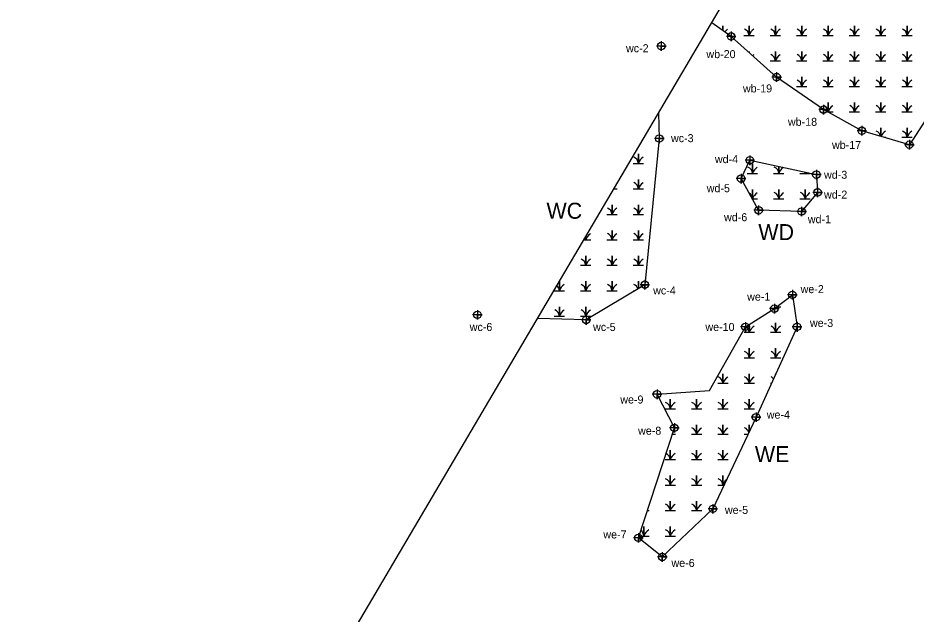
# Model space of a CAD drawing. Extents: x 2379288 to 2381905, y 330670 to 333511.
# Drawn here: x 2379288 to 2379849, y 331240 to 331613 of the extents above; entities that cross this region are included whole.
import ezdxf

# ---------------------------------------------------------------- set-up
doc = ezdxf.new("R2010")
doc.units = 0
for name, color, linetype in [('Default', 7, 'Continuous'), ('Exist Environmental Wetland Boundary', 7, 'Continuous'), ('Exist Environmental Wetland Boundary Cogo Number', 7, 'Continuous'), ('Exist Environmental Wetland Boundary Cogo Point CELL', 7, 'Continuous'), ('Exist Environmental Wetland Boundary Text', 7, 'Continuous'), ('Exist Hydro Swamp or Marsh', 7, 'Continuous')]:
    doc.layers.add(name, color=color, linetype=linetype)

msp = doc.modelspace()

# ---------------------------------------------------------------- linework, layer by layer
at = {"layer": 'Default'}
msp.add_lwpolyline([(2380453.94, 332065.55), (2379632.78, 330670.47), (2379288.07, 330873.37), (2380109.3, 332268.58)], dxfattribs=at)
at = {"layer": 'Exist Environmental Wetland Boundary'}
for points in [[(2380130.29, 332029.9), (2380102.32, 331972.59), (2380055.88, 331898.56), (2380034.74, 331855.71), (2379997.28, 331799.99), (2379955.67, 331743.45), (2379938.98, 331697.47), (2379905.07, 331626.66), (2379844.93, 331533.46), (2379815.25, 331542.18), (2379791.29, 331555.41), (2379761.99, 331575.7), (2379733.64, 331601.14), (2379721.48, 331609.71)], [(2379688.21, 331553.19), (2379688.73, 331537.29), (2379679.7, 331445.96), (2379643.04, 331423.91), (2379612.62, 331424.77)]]:
    msp.add_lwpolyline(points, dxfattribs=at)
for points in [[(2379777.65, 331491.7), (2379750.74, 331492.47), (2379739.83, 331512.28), (2379745.27, 331523.73), (2379786.87, 331514.73), (2379787.62, 331503.6)], [(2379760.62, 331430.97), (2379771.84, 331439.64), (2379774.79, 331419.58), (2379749.19, 331363.16), (2379722.16, 331305.85), (2379690.58, 331275.83), (2379675.68, 331287.73), (2379698.12, 331356.48), (2379687.35, 331377.45), (2379720.1, 331379.72), (2379742.49, 331419.61)]]:
    msp.add_lwpolyline(points, close=True, dxfattribs=at)
at = {"layer": 'Exist Environmental Wetland Boundary Cogo Point CELL'}
for points in [[(2379733.64, 331604.14), (2379733.64, 331598.14), (2379733.64, 331601.14), (2379736.64, 331601.14), (2379730.64, 331601.14)], [(2379689.98, 331598.11), (2379689.98, 331592.11), (2379689.98, 331595.11), (2379692.98, 331595.11), (2379686.98, 331595.11)], [(2379761.99, 331578.7), (2379761.99, 331572.7), (2379761.99, 331575.7), (2379764.99, 331575.7), (2379758.99, 331575.7)], [(2379791.29, 331558.41), (2379791.29, 331552.41), (2379791.29, 331555.41), (2379794.29, 331555.41), (2379788.29, 331555.41)], [(2379815.25, 331545.18), (2379815.25, 331539.18), (2379815.25, 331542.18), (2379818.25, 331542.18), (2379812.25, 331542.18)], [(2379688.73, 331540.29), (2379688.73, 331534.29), (2379688.73, 331537.29), (2379691.73, 331537.29), (2379685.73, 331537.29)], [(2379844.93, 331536.46), (2379844.93, 331530.46), (2379844.93, 331533.46), (2379847.93, 331533.46), (2379841.93, 331533.46)], [(2379745.27, 331526.73), (2379745.27, 331520.73), (2379745.27, 331523.73), (2379748.27, 331523.73), (2379742.27, 331523.73)], [(2379739.83, 331515.28), (2379739.83, 331509.28), (2379739.83, 331512.28), (2379742.83, 331512.28), (2379736.83, 331512.28)], [(2379786.87, 331517.73), (2379786.87, 331511.73), (2379786.87, 331514.73), (2379789.87, 331514.73), (2379783.87, 331514.73)], [(2379787.62, 331506.6), (2379787.62, 331500.6), (2379787.62, 331503.6), (2379790.62, 331503.6), (2379784.62, 331503.6)], [(2379750.74, 331495.47), (2379750.74, 331489.47), (2379750.74, 331492.47), (2379753.74, 331492.47), (2379747.74, 331492.47)], [(2379777.65, 331494.7), (2379777.65, 331488.7), (2379777.65, 331491.7), (2379780.65, 331491.7), (2379774.65, 331491.7)], [(2379679.7, 331448.96), (2379679.7, 331442.96), (2379679.7, 331445.96), (2379682.7, 331445.96), (2379676.7, 331445.96)], [(2379771.84, 331442.64), (2379771.84, 331436.64), (2379771.84, 331439.64), (2379774.84, 331439.64), (2379768.84, 331439.64)], [(2379575.08, 331430.12), (2379575.08, 331424.12), (2379575.08, 331427.12), (2379578.08, 331427.12), (2379572.08, 331427.12)], [(2379760.62, 331433.97), (2379760.62, 331427.97), (2379760.62, 331430.97), (2379763.62, 331430.97), (2379757.62, 331430.97)], [(2379643.04, 331426.91), (2379643.04, 331420.91), (2379643.04, 331423.91), (2379646.04, 331423.91), (2379640.04, 331423.91)], [(2379742.49, 331422.61), (2379742.49, 331416.61), (2379742.49, 331419.61), (2379745.49, 331419.61), (2379739.49, 331419.61)], [(2379774.79, 331422.58), (2379774.79, 331416.58), (2379774.79, 331419.58), (2379777.79, 331419.58), (2379771.79, 331419.58)], [(2379687.35, 331380.45), (2379687.35, 331374.45), (2379687.35, 331377.45), (2379690.35, 331377.45), (2379684.35, 331377.45)], [(2379749.19, 331366.16), (2379749.19, 331360.16), (2379749.19, 331363.16), (2379752.19, 331363.16), (2379746.19, 331363.16)], [(2379698.12, 331359.48), (2379698.12, 331353.48), (2379698.12, 331356.48), (2379701.12, 331356.48), (2379695.12, 331356.48)], [(2379722.16, 331308.85), (2379722.16, 331302.85), (2379722.16, 331305.85), (2379725.16, 331305.85), (2379719.16, 331305.85)], [(2379675.68, 331290.73), (2379675.68, 331284.73), (2379675.68, 331287.73), (2379678.68, 331287.73), (2379672.68, 331287.73)], [(2379690.58, 331278.83), (2379690.58, 331272.83), (2379690.58, 331275.83), (2379693.58, 331275.83), (2379687.58, 331275.83)]]:
    msp.add_lwpolyline(points, dxfattribs=at)
for centre in [(2379733.64, 331601.14), (2379689.98, 331595.11), (2379761.99, 331575.7), (2379791.29, 331555.41), (2379815.25, 331542.18), (2379688.73, 331537.29), (2379844.93, 331533.46), (2379745.27, 331523.73), (2379739.83, 331512.28), (2379786.87, 331514.73), (2379787.62, 331503.6), (2379750.74, 331492.47), (2379777.65, 331491.7), (2379679.7, 331445.96), (2379771.84, 331439.64), (2379575.08, 331427.12), (2379760.62, 331430.97), (2379643.04, 331423.91), (2379742.49, 331419.61), (2379774.79, 331419.58), (2379687.35, 331377.45), (2379749.19, 331363.16), (2379698.12, 331356.48), (2379722.16, 331305.85), (2379675.68, 331287.73), (2379690.58, 331275.83)]:
    msp.add_circle(centre, 2.34, dxfattribs=at)
at = {"layer": 'Exist Hydro Swamp or Marsh'}
for p, q in [((2379829.24, 331538.07), (2379830.29, 331538.07)), ((2379660.34, 331505.83), (2379662.46, 331505.83)), ((2379672.46, 331442.16), (2379673.37, 331442.16)), ((2379762.11, 331432.12), (2379764.57, 331432.12)), ((2379731.64, 331400.28), (2379731.67, 331400.28)), ((2379758.12, 331384.36), (2379758.81, 331384.36)), ((2379696.83, 331352.53), (2379698.77, 331352.53)), ((2379741.67, 331352.53), (2379744.18, 331352.53)), ((2379681.25, 331304.77), (2379682.31, 331304.77))]:
    msp.add_line(p, q, dxfattribs=at)
for points in [[(2379728.35, 331604.87), (2379728.35, 331607.66), (2379728.35, 331604.87)], [(2379741.58, 331601.74), (2379744.81, 331601.74), (2379744.81, 331607.66), (2379744.81, 331601.74), (2379748.03, 331601.74)], [(2379758.03, 331601.74), (2379761.26, 331601.74), (2379761.26, 331607.66), (2379761.26, 331601.74), (2379764.48, 331601.74)], [(2379774.48, 331601.74), (2379777.71, 331601.74), (2379777.71, 331607.66), (2379777.71, 331601.74), (2379780.93, 331601.74)], [(2379790.93, 331601.74), (2379794.16, 331601.74), (2379794.16, 331607.66), (2379794.16, 331601.74), (2379797.39, 331601.74)], [(2379807.39, 331601.74), (2379810.61, 331601.74), (2379810.61, 331607.66), (2379810.61, 331601.74), (2379813.84, 331601.74)], [(2379823.84, 331601.74), (2379827.06, 331601.74), (2379827.06, 331607.66), (2379827.06, 331601.74), (2379830.29, 331601.74)], [(2379840.29, 331601.74), (2379843.51, 331601.74), (2379843.51, 331607.66), (2379843.51, 331601.74), (2379846.74, 331601.74)], [(2379744.81, 331591.12), (2379744.81, 331591.74), (2379744.81, 331591.12)], [(2379758.03, 331585.82), (2379761.26, 331585.82), (2379761.26, 331591.74), (2379761.26, 331585.82), (2379764.48, 331585.82)], [(2379774.48, 331585.82), (2379777.71, 331585.82), (2379777.71, 331591.74), (2379777.71, 331585.82), (2379780.93, 331585.82)], [(2379790.93, 331585.82), (2379794.16, 331585.82), (2379794.16, 331591.74), (2379794.16, 331585.82), (2379797.39, 331585.82)], [(2379807.39, 331585.82), (2379810.61, 331585.82), (2379810.61, 331591.74), (2379810.61, 331585.82), (2379813.84, 331585.82)], [(2379823.84, 331585.82), (2379827.06, 331585.82), (2379827.06, 331591.74), (2379827.06, 331585.82), (2379830.29, 331585.82)], [(2379840.29, 331585.82), (2379843.51, 331585.82), (2379843.51, 331591.74), (2379843.51, 331585.82), (2379846.74, 331585.82)], [(2379774.48, 331569.9), (2379777.71, 331569.9), (2379777.71, 331575.82), (2379777.71, 331569.9), (2379780.93, 331569.9)], [(2379790.93, 331569.9), (2379794.16, 331569.9), (2379794.16, 331575.82), (2379794.16, 331569.9), (2379797.39, 331569.9)], [(2379807.39, 331569.9), (2379810.61, 331569.9), (2379810.61, 331575.82), (2379810.61, 331569.9), (2379813.84, 331569.9)], [(2379823.84, 331569.9), (2379827.06, 331569.9), (2379827.06, 331575.82), (2379827.06, 331569.9), (2379830.29, 331569.9)], [(2379840.29, 331569.9), (2379843.51, 331569.9), (2379843.51, 331575.82), (2379843.51, 331569.9), (2379846.74, 331569.9)], [(2379793.87, 331553.99), (2379794.16, 331553.99), (2379794.16, 331559.9), (2379794.16, 331553.99), (2379797.39, 331553.99)], [(2379807.39, 331553.99), (2379810.61, 331553.99), (2379810.61, 331559.9), (2379810.61, 331553.99), (2379813.84, 331553.99)], [(2379823.84, 331553.99), (2379827.06, 331553.99), (2379827.06, 331559.9), (2379827.06, 331553.99), (2379830.29, 331553.99)], [(2379840.29, 331553.99), (2379843.51, 331553.99), (2379843.51, 331559.9), (2379843.51, 331553.99), (2379846.74, 331553.99)], [(2379827.06, 331538.71), (2379827.06, 331543.99), (2379827.06, 331538.71)], [(2379840.29, 331538.07), (2379843.51, 331538.07), (2379843.51, 331543.99), (2379843.51, 331538.07), (2379846.74, 331538.07)], [(2379672.46, 331521.74), (2379675.68, 331521.74), (2379675.68, 331527.66), (2379675.68, 331521.74), (2379678.91, 331521.74)], [(2379743.71, 331515.53), (2379746.94, 331515.53), (2379746.94, 331521.45), (2379746.94, 331515.53), (2379750.16, 331515.53)], [(2379760.16, 331515.53), (2379763.39, 331515.53), (2379763.39, 331519.81)], [(2379763.39, 331519.81), (2379763.39, 331515.53), (2379766.62, 331515.53)], [(2379776.62, 331515.53), (2379779.84, 331515.53), (2379779.84, 331516.25)], [(2379779.84, 331516.25), (2379779.84, 331515.53), (2379783.07, 331515.53)], [(2379672.46, 331505.83), (2379675.68, 331505.83), (2379675.68, 331511.74), (2379675.68, 331505.83), (2379678.91, 331505.83)], [(2379746.8, 331499.61), (2379746.94, 331499.61), (2379746.94, 331505.53), (2379746.94, 331499.61), (2379750.16, 331499.61)], [(2379760.16, 331499.61), (2379763.39, 331499.61), (2379763.39, 331505.53), (2379763.39, 331499.61), (2379766.62, 331499.61)], [(2379776.62, 331499.61), (2379779.84, 331499.61), (2379779.84, 331505.53), (2379779.84, 331499.61), (2379783.07, 331499.61)], [(2379656.01, 331489.91), (2379659.23, 331489.91), (2379659.23, 331495.83), (2379659.23, 331489.91), (2379662.46, 331489.91)], [(2379672.46, 331489.91), (2379675.68, 331489.91), (2379675.68, 331495.83), (2379675.68, 331489.91), (2379678.91, 331489.91)], [(2379656.01, 331473.99), (2379659.23, 331473.99), (2379659.23, 331479.91), (2379659.23, 331473.99), (2379662.46, 331473.99)], [(2379672.46, 331473.99), (2379675.68, 331473.99), (2379675.68, 331479.91), (2379675.68, 331473.99), (2379678.91, 331473.99)], [(2379641.6, 331473.99), (2379642.78, 331473.99), (2379642.78, 331476)], [(2379642.78, 331476), (2379642.78, 331473.99), (2379646.01, 331473.99)], [(2379639.55, 331458.07), (2379642.78, 331458.07), (2379642.78, 331463.99), (2379642.78, 331458.07), (2379646.01, 331458.07)], [(2379656.01, 331458.07), (2379659.23, 331458.07), (2379659.23, 331463.99), (2379659.23, 331458.07), (2379662.46, 331458.07)], [(2379672.46, 331458.07), (2379675.68, 331458.07), (2379675.68, 331463.99), (2379675.68, 331458.07), (2379678.91, 331458.07)], [(2379623.1, 331442.16), (2379626.33, 331442.16), (2379626.33, 331448.05)], [(2379626.33, 331448.05), (2379626.33, 331442.16), (2379629.55, 331442.16)], [(2379639.55, 331442.16), (2379642.78, 331442.16), (2379642.78, 331448.07), (2379642.78, 331442.16), (2379646.01, 331442.16)], [(2379656.01, 331442.16), (2379659.23, 331442.16), (2379659.23, 331448.07), (2379659.23, 331442.16), (2379662.46, 331442.16)], [(2379675.68, 331443.55), (2379675.68, 331448.07), (2379675.68, 331443.55)], [(2379623.1, 331426.24), (2379626.33, 331426.24), (2379626.33, 331432.16), (2379626.33, 331426.24), (2379629.55, 331426.24)], [(2379639.55, 331426.24), (2379642.78, 331426.24), (2379642.78, 331432.16), (2379642.78, 331426.24), (2379646.01, 331426.24)], [(2379741.67, 331416.2), (2379744.89, 331416.2), (2379744.89, 331421.12)], [(2379744.89, 331421.12), (2379744.89, 331416.2), (2379748.12, 331416.2)], [(2379758.12, 331416.2), (2379761.35, 331416.2), (2379761.35, 331422.12), (2379761.35, 331416.2), (2379764.57, 331416.2)], [(2379741.67, 331400.28), (2379744.89, 331400.28), (2379744.89, 331406.2), (2379744.89, 331400.28), (2379748.12, 331400.28)], [(2379758.12, 331400.28), (2379761.35, 331400.28), (2379761.35, 331406.2), (2379761.35, 331400.28), (2379764.57, 331400.28)], [(2379725.22, 331384.36), (2379728.44, 331384.36), (2379728.44, 331390.28), (2379728.44, 331384.36), (2379731.67, 331384.36)], [(2379741.67, 331384.36), (2379744.89, 331384.36), (2379744.89, 331390.28), (2379744.89, 331384.36), (2379748.12, 331384.36)], [(2379761.35, 331389.95), (2379761.35, 331390.28), (2379761.35, 331389.95)], [(2379692.31, 331368.45), (2379695.54, 331368.45), (2379695.54, 331374.36), (2379695.54, 331368.45), (2379698.77, 331368.45)], [(2379708.77, 331368.45), (2379711.99, 331368.45), (2379711.99, 331374.36), (2379711.99, 331368.45), (2379715.22, 331368.45)], [(2379725.22, 331368.45), (2379728.44, 331368.45), (2379728.44, 331374.36), (2379728.44, 331368.45), (2379731.67, 331368.45)], [(2379741.67, 331368.45), (2379744.89, 331368.45), (2379744.89, 331374.36), (2379744.89, 331368.45), (2379748.12, 331368.45)], [(2379708.77, 331352.53), (2379711.99, 331352.53), (2379711.99, 331358.45), (2379711.99, 331352.53), (2379715.22, 331352.53)], [(2379725.22, 331352.53), (2379728.44, 331352.53), (2379728.44, 331358.45), (2379728.44, 331352.53), (2379731.67, 331352.53)], [(2379744.89, 331354.05), (2379744.89, 331358.45), (2379744.89, 331354.05)], [(2379692.31, 331336.61), (2379695.54, 331336.61), (2379695.54, 331342.53), (2379695.54, 331336.61), (2379698.77, 331336.61)], [(2379708.77, 331336.61), (2379711.99, 331336.61), (2379711.99, 331342.53), (2379711.99, 331336.61), (2379715.22, 331336.61)], [(2379725.22, 331336.61), (2379728.44, 331336.61), (2379728.44, 331342.53), (2379728.44, 331336.61), (2379731.67, 331336.61)], [(2379692.31, 331320.69), (2379695.54, 331320.69), (2379695.54, 331326.61), (2379695.54, 331320.69), (2379698.77, 331320.69)], [(2379708.77, 331320.69), (2379711.99, 331320.69), (2379711.99, 331326.61), (2379711.99, 331320.69), (2379715.22, 331320.69)], [(2379725.22, 331320.69), (2379728.44, 331320.69), (2379728.44, 331326.61), (2379728.44, 331320.69), (2379729.16, 331320.69)], [(2379692.31, 331304.77), (2379695.54, 331304.77), (2379695.54, 331310.69), (2379695.54, 331304.77), (2379698.77, 331304.77)], [(2379708.77, 331304.77), (2379711.99, 331304.77), (2379711.99, 331310.69), (2379711.99, 331304.77), (2379715.22, 331304.77)], [(2379676.05, 331288.86), (2379679.09, 331288.86), (2379679.09, 331294.77), (2379679.09, 331288.86), (2379682.31, 331288.86)], [(2379692.31, 331288.86), (2379695.54, 331288.86), (2379695.54, 331294.77), (2379695.54, 331288.86), (2379698.77, 331288.86)]]:
    msp.add_lwpolyline(points, dxfattribs=at)
for centre, radius, start, end in [((2379735.2, 331599.47), 7.21, 122.1274, 141.0614), ((2379740.21, 331601.41), 4.61, 4.1403, 67.535), ((2379751.65, 331599.47), 7.21, 122.1274, 161.6222), ((2379756.66, 331601.41), 4.61, 4.1403, 67.535), ((2379768.1, 331599.47), 7.21, 122.1274, 161.6222), ((2379773.11, 331601.41), 4.61, 4.1403, 67.535), ((2379784.55, 331599.47), 7.21, 122.1274, 161.6222), ((2379789.56, 331601.41), 4.61, 4.1403, 67.535), ((2379801, 331599.47), 7.21, 122.1274, 161.6222), ((2379806.01, 331601.41), 4.61, 4.1403, 67.535), ((2379817.45, 331599.47), 7.21, 122.1274, 161.6222), ((2379822.46, 331601.41), 4.61, 4.1403, 67.535), ((2379833.9, 331599.47), 7.21, 122.1274, 161.6222), ((2379838.91, 331601.41), 4.61, 4.1403, 67.535), ((2379850.35, 331599.47), 7.21, 122.1274, 161.6222), ((2379751.65, 331583.55), 7.21, 122.1274, 129.6032), ((2379756.66, 331585.49), 4.61, 4.1403, 67.535), ((2379768.1, 331583.55), 7.21, 122.1274, 161.6222), ((2379773.11, 331585.49), 4.61, 4.1403, 67.535), ((2379784.55, 331583.55), 7.21, 122.1274, 161.6222), ((2379789.56, 331585.49), 4.61, 4.1403, 67.535), ((2379801, 331583.55), 7.21, 122.1274, 161.6222), ((2379806.01, 331585.49), 4.61, 4.1403, 67.535), ((2379817.45, 331583.55), 7.21, 122.1274, 161.6222), ((2379822.46, 331585.49), 4.61, 4.1403, 67.535), ((2379833.9, 331583.55), 7.21, 122.1274, 161.6222), ((2379838.91, 331585.49), 4.61, 4.1403, 67.535), ((2379850.35, 331583.55), 7.21, 122.1274, 161.6222), ((2379773.11, 331569.57), 4.61, 4.1403, 67.535), ((2379784.55, 331567.63), 7.21, 122.1274, 161.6222), ((2379789.56, 331569.57), 4.61, 4.1403, 67.535), ((2379801, 331567.63), 7.21, 122.1274, 161.6222), ((2379806.01, 331569.57), 4.61, 4.1403, 67.535), ((2379817.45, 331567.63), 7.21, 122.1274, 161.6222), ((2379822.46, 331569.57), 4.61, 4.1403, 67.535), ((2379833.9, 331567.63), 7.21, 122.1274, 161.6222), ((2379838.91, 331569.57), 4.61, 4.1403, 67.535), ((2379850.35, 331567.63), 7.21, 122.1274, 161.6222), ((2379789.56, 331553.65), 4.61, 4.1403, 67.535), ((2379801, 331551.71), 7.21, 122.1274, 161.6222), ((2379806.01, 331553.65), 4.61, 4.1403, 67.535), ((2379817.45, 331551.71), 7.21, 122.1274, 161.6222), ((2379822.46, 331553.65), 4.61, 4.1403, 67.535), ((2379833.9, 331551.71), 7.21, 122.1274, 161.6222), ((2379838.91, 331553.65), 4.61, 4.1403, 67.535), ((2379850.35, 331551.71), 7.21, 122.1274, 161.6222), ((2379822.46, 331537.74), 4.61, 12.5359, 67.535), ((2379833.9, 331535.8), 7.21, 122.1274, 156.7309), ((2379838.91, 331537.74), 4.61, 4.1403, 67.535), ((2379850.35, 331535.8), 7.21, 122.1274, 161.6222), ((2379671.08, 331521.41), 4.61, 4.1403, 67.535), ((2379682.52, 331519.47), 7.21, 122.1274, 161.6222), ((2379742.34, 331515.2), 4.61, 4.1403, 67.535), ((2379753.78, 331513.26), 7.21, 122.1274, 161.6222), ((2379758.79, 331515.2), 4.61, 4.1403, 67.535), ((2379770.23, 331513.26), 7.21, 124.3472, 161.6222), ((2379775.24, 331515.2), 4.61, 4.1403, 13.4778), ((2379786.68, 331513.26), 7.21, 155.9808, 161.6222), ((2379671.08, 331505.49), 4.61, 4.1403, 67.535), ((2379682.52, 331503.55), 7.21, 122.1274, 161.6222), ((2379742.34, 331499.28), 4.61, 4.1403, 56.793), ((2379753.78, 331497.34), 7.21, 122.1274, 161.6222), ((2379758.79, 331499.28), 4.61, 4.1403, 67.535), ((2379770.23, 331497.34), 7.21, 122.1274, 161.6222), ((2379775.24, 331499.28), 4.61, 4.1403, 67.535), ((2379786.68, 331497.34), 7.21, 122.1274, 161.6222), ((2379654.63, 331489.58), 4.61, 4.1403, 67.535), ((2379666.07, 331487.64), 7.21, 122.1274, 161.6222), ((2379671.08, 331489.58), 4.61, 4.1403, 67.535), ((2379682.52, 331487.64), 7.21, 122.1274, 161.6222), ((2379638.18, 331473.66), 4.61, 4.1403, 22.5161), ((2379649.62, 331471.72), 7.21, 122.1274, 161.6222), ((2379654.63, 331473.66), 4.61, 4.1403, 67.535), ((2379666.07, 331471.72), 7.21, 122.1274, 161.6222), ((2379671.08, 331473.66), 4.61, 4.1403, 67.535), ((2379682.52, 331471.72), 7.21, 122.1274, 161.6222), ((2379638.18, 331457.74), 4.61, 4.1403, 67.535), ((2379649.62, 331455.8), 7.21, 122.1274, 161.6222), ((2379654.63, 331457.74), 4.61, 4.1403, 67.535), ((2379666.07, 331455.8), 7.21, 122.1274, 161.6222), ((2379671.08, 331457.74), 4.61, 4.1403, 67.535), ((2379682.52, 331455.8), 7.21, 122.1274, 161.6222), ((2379621.73, 331441.82), 4.61, 4.1403, 49.4728), ((2379633.17, 331439.88), 7.21, 122.1274, 161.6222), ((2379638.18, 331441.82), 4.61, 4.1403, 67.535), ((2379649.62, 331439.88), 7.21, 122.1274, 161.6222), ((2379654.63, 331441.82), 4.61, 4.1403, 67.535), ((2379666.07, 331439.88), 7.21, 122.1274, 161.6222), ((2379671.08, 331441.82), 4.61, 19.8594, 67.535), ((2379682.52, 331439.88), 7.21, 122.1274, 143.3993), ((2379621.73, 331425.91), 4.61, 4.1403, 67.535), ((2379633.17, 331423.97), 7.21, 122.1274, 161.6222), ((2379638.18, 331425.91), 4.61, 4.1403, 67.535), ((2379649.62, 331423.97), 7.21, 122.1274, 161.6222), ((2379740.29, 331415.87), 4.61, 4.1403, 57.9069), ((2379751.73, 331413.93), 7.21, 122.1274, 161.6222), ((2379756.75, 331415.87), 4.61, 4.1403, 67.535), ((2379768.19, 331413.93), 7.21, 122.1274, 161.6222), ((2379740.29, 331399.95), 4.61, 4.1403, 67.535), ((2379751.73, 331398.01), 7.21, 122.1274, 161.6222), ((2379756.75, 331399.95), 4.61, 4.1403, 67.535), ((2379768.19, 331398.01), 7.21, 122.1274, 161.6222), ((2379723.84, 331384.03), 4.61, 4.1403, 67.535), ((2379735.28, 331382.09), 7.21, 122.1274, 161.6222), ((2379740.29, 331384.03), 4.61, 4.1403, 67.535), ((2379751.73, 331382.09), 7.21, 122.1274, 161.6222), ((2379756.75, 331384.03), 4.61, 43.3815, 67.535), ((2379690.94, 331368.11), 4.61, 4.1403, 67.535), ((2379707.39, 331368.11), 4.61, 4.1403, 67.535), ((2379723.84, 331368.11), 4.61, 4.1403, 67.535), ((2379740.29, 331368.11), 4.61, 4.1403, 67.535), ((2379702.38, 331366.17), 7.21, 122.1274, 161.6222), ((2379718.83, 331366.17), 7.21, 122.1274, 161.6222), ((2379735.28, 331366.17), 7.21, 122.1274, 161.6222), ((2379751.73, 331366.17), 7.21, 122.1274, 161.6222), ((2379702.38, 331350.25), 7.21, 122.1274, 127.9495), ((2379707.39, 331352.19), 4.61, 4.1403, 67.535), ((2379718.83, 331350.25), 7.21, 122.1274, 161.6222), ((2379723.84, 331352.19), 4.61, 4.1403, 67.535), ((2379735.28, 331350.25), 7.21, 122.1274, 161.6222), ((2379740.29, 331352.19), 4.61, 17.8212, 67.535), ((2379690.94, 331336.28), 4.61, 4.1403, 64.9381), ((2379702.38, 331334.34), 7.21, 122.1274, 161.6222), ((2379707.39, 331336.28), 4.61, 4.1403, 67.535), ((2379718.83, 331334.34), 7.21, 122.1274, 161.6222), ((2379723.84, 331336.28), 4.61, 4.1403, 67.535), ((2379735.28, 331334.34), 7.21, 122.1274, 161.6222), ((2379690.94, 331320.36), 4.61, 4.1403, 67.535), ((2379702.38, 331318.42), 7.21, 122.1274, 161.6222), ((2379707.39, 331320.36), 4.61, 4.1403, 67.535), ((2379718.83, 331318.42), 7.21, 122.1274, 161.6222), ((2379723.84, 331320.36), 4.61, 4.1403, 67.535), ((2379735.28, 331318.42), 7.21, 129.2954, 161.6222), ((2379690.94, 331304.44), 4.61, 4.1403, 67.535), ((2379702.38, 331302.5), 7.21, 122.1274, 161.6222), ((2379707.39, 331304.44), 4.61, 4.1403, 67.535), ((2379718.83, 331302.5), 7.21, 122.1274, 161.6222), ((2379674.49, 331288.52), 4.61, 4.1403, 54.4748), ((2379685.93, 331286.58), 7.21, 122.1274, 161.6222), ((2379690.94, 331288.52), 4.61, 4.1403, 67.535), ((2379702.38, 331286.58), 7.21, 122.1274, 161.6222)]:
    msp.add_arc(centre, radius, start, end, dxfattribs=at)

# ---------------------------------------------------------------- texts
at = {"layer": 'Exist Environmental Wetland Boundary Cogo Number'}
for s, p in [('wc-2', (2379667.93, 331591.24)), ('wb-20', (2379718.16, 331587.54)), ('wb-19', (2379740.98, 331566.12)), ('wb-18', (2379769.08, 331545.24)), ('wc-3', (2379696.03, 331535.03)), ('wb-17', (2379796.62, 331530.77)), ('wd-4', (2379723.45, 331521.91)), ('wd-3', (2379791.64, 331512.16)), ('wd-5', (2379718.36, 331503.74)), ('wd-2', (2379791.64, 331499.76)), ('wd-6', (2379729.17, 331485.61)), ('wd-1', (2379781.52, 331484.38)), ('we-2', (2379777.01, 331440.69)), ('wc-4', (2379684.9, 331439.85)), ('we-1', (2379743.61, 331435.96)), ('we-3', (2379782.85, 331419.54)), ('wc-6', (2379570.29, 331417.03)), ('wc-5', (2379647.34, 331417.03)), ('we-10', (2379717.53, 331417.04)), ('we-9', (2379664.34, 331371.68)), ('we-4', (2379755.86, 331362.21)), ('we-8', (2379675.47, 331352.2)), ('we-5', (2379729.71, 331302.66)), ('we-7', (2379653.77, 331287.35)), ('we-6', (2379696.33, 331269.54))]:
    msp.add_text(s, height=5, dxfattribs=at).set_placement(p)
at = {"layer": 'Exist Environmental Wetland Boundary Text'}
for s, p in [('WC', (2379618.26, 331487.16)), ('WD', (2379750.6, 331473.81)), ('WE', (2379748.45, 331335.03))]:
    msp.add_text(s, height=10, dxfattribs=at).set_placement(p)

doc.saveas('drawing.dxf')
